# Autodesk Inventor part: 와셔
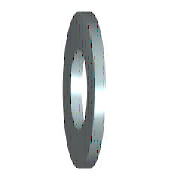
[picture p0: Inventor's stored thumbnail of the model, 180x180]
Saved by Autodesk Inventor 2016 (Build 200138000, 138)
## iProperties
IsCustomPart: 1
Created: 2012-02
Part Number: 와셔
Material: 강철, 연강
Description: 평면 와셔
Document SubType Name: Modeling
Standard: KS B 1326
Designer: mduedu
Standards Organization: KS
Language: ko-KR
Size Designation: 8x15.5
Categories: <MemberInstance><Categories><Category DisplayName="조임쇠" InternalName="e4da775c-781d-43d5-af7c-5136215cf5a6" Mnemonic="FSTN"><Category DisplayName="와셔" InternalN
Density: 1 g/cm^3
Appearance: 주황색
Author: mduedu
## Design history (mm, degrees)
sketch "스케치"
  geometry: C1 r 7.75 at (0, 0); C2 r 4.2 at (0, 0); 1 further point
  constraints: 2 centre point, 2 coincident
  dimensions: "d0" = 8.4 diameter of C2 (= SD1); "d1" = 15.5 diameter of C1 (= SD2)
extrude "본체" new body sketch "스케치" distance "d2" = 1.6 (= SD); taper "d3" = 0 deg
workaxis "Work Axis1"
workplane "Work Plane1"
body "Solid1"
other parameters: "SD1" = 8.4 [user parameter; used in 1 equation term], "SD2" = 15.5 [user parameter; used in 1 equation term], "SD" = 1.6 [user parameter; used in 1 equation term], "d4" = 0, "d5" = 0, "d6" = 0, "d7" = 0, "NND" = 8 [user parameter]
